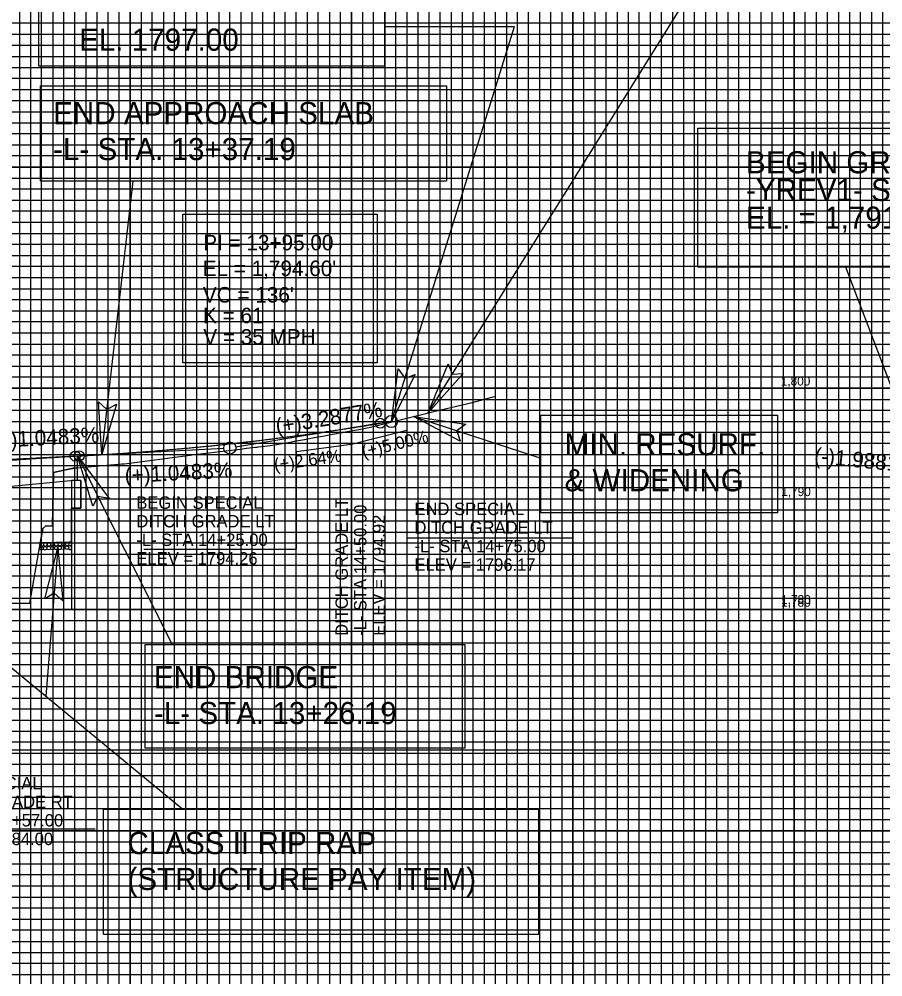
# Model space of a CAD drawing. Extents: x 572269 to 579912, y -56875 to -49627.
# Drawn here: x 574184.5 to 574574.7, y -53513.8 to -53080.9 of the extents above; entities that cross this region are included whole.
import ezdxf

# ---------------------------------------------------------------- set-up
doc = ezdxf.new("R2010")
doc.units = 0
for name, color, linetype in [('Default', 7, 'Continuous'), ('Exist Profile Cell', 7, 'Continuous'), ('Exist Vertical Profile Ground Line', 7, 'Continuous'), ('Pattern 9', 7, 'Continuous'), ('Prop Grid Mask', 7, 'Continuous'), ('Prop PFL Text', 7, 'Continuous'), ('Prop Rip Rap Related Quantities Text', 7, 'Continuous'), ('Prop Roadway Bridge', 7, 'Continuous'), ('Prop Vertical Profile Curve Label', 7, 'Continuous'), ('Prop Vertical Profile Ditch Grade Left', 7, 'Continuous'), ('Prop Vertical Profile Ditch Grade Left Label', 7, 'Continuous'), ('Prop Vertical Profile Ditch Grade Right Label', 7, 'Continuous'), ('Prop Vertical Profile Grade', 7, 'Continuous'), ('Prop Vertical Profile Grade Label', 7, 'Continuous'), ('Prop VPI Label', 7, 'Continuous'), ('Scratch_Level_0', 7, 'Continuous'), ('Scratch_Level_6', 7, 'Continuous'), ('Sheet Cutting Line CELL', 7, 'Continuous'), ('Sheet DOT Grid CELL', 7, 'Continuous'), ('Sheet Profile Grid Major CELL', 7, 'Continuous'), ('Sheet Profile Grid Middle CELL', 7, 'Continuous'), ('Sheet Profile Grid Minor CELL', 7, 'Continuous'), ('Typical Terminator CELL', 7, 'Continuous')]:
    doc.layers.add(name, color=color, linetype=linetype)

# ---------------------------------------------------------------- blocks, each defined once
blk = doc.blocks.new('TERMINATOR')
at = {"layer": 'Typical Terminator CELL'}
blk.add_lwpolyline([(-0.4687, 0.0807), (0, 0), (-0.4713, -0.0833), (-0.4114, 0)], close=True, dxfattribs=at)
blk = doc.blocks.new('PROFILE SHEET SINGLE')
at = {"layer": 'Sheet DOT Grid CELL'}
for p, q in [((7, 21), (7, 0.5)), ((8, 21), (8, 0.5)), ((9, 21), (9, 0.5)), ((10, 21), (10, 0.5)), ((11, 21), (11, 0.5)), ((12, 21), (12, 0.5)), ((13, 21), (13, 0.5)), ((14, 21), (14, 0.5)), ((0, 14.5), (30, 14.5)), ((0, 13.5), (30, 13.5)), ((0, 12.5), (30, 12.5)), ((0, 11.5), (30, 11.5)), ((0, 10.5), (30, 10.5)), ((0, 9.5), (30, 9.5)), ((0, 8.5), (30, 8.5)), ((0, 7.5), (30, 7.5)), ((0, 6.5), (30, 6.5))]:
    blk.add_line(p, q, dxfattribs=at)
at = {"layer": 'Sheet Profile Grid Major CELL'}
for points in [[(7, 21), (7, 0.5), (8, 0.5), (8, 21)], [(9, 21), (9, 0.5), (10, 0.5), (10, 21)], [(11, 21), (11, 0.5), (12, 0.5), (12, 21)], [(13, 21), (13, 0.5), (14, 0.5), (14, 21)], [(30, 13.5), (0, 13.5), (0, 14.5), (30, 14.5)], [(30, 11.5), (0, 11.5), (0, 12.5), (30, 12.5)], [(30, 9.5), (0, 9.5), (0, 10.5), (30, 10.5)], [(30, 7.5), (0, 7.5), (0, 8.5), (30, 8.5)], [(30, 5.5), (0, 5.5), (0, 6.5), (30, 6.5)]]:
    blk.add_lwpolyline(points, dxfattribs=at)
at = {"layer": 'Sheet Profile Grid Middle CELL'}
for points in [[(6.5, 21), (6.5, 0.5), (7.5, 0.5), (7.5, 21)], [(8.5, 21), (8.5, 0.5), (9.5, 0.5), (9.5, 21)], [(10.5, 21), (10.5, 0.5), (11.5, 0.5), (11.5, 21)], [(12.5, 21), (12.5, 0.5), (13.5, 0.5), (13.5, 21)], [(14.5, 21), (14.5, 0.5), (15.5, 0.5), (15.5, 21)], [(30, 15), (0, 15), (0, 14), (30, 14)], [(30, 13), (0, 13), (0, 12), (30, 12)], [(30, 11), (0, 11), (0, 10), (30, 10)], [(30, 9), (0, 9), (0, 8), (30, 8)], [(30, 7), (0, 7), (0, 6), (30, 6)]]:
    blk.add_lwpolyline(points, dxfattribs=at)
at = {"layer": 'Sheet Profile Grid Minor CELL'}
for points in [[(7.1, 21), (7.1, 0.5), (7.2, 0.5), (7.2, 21)], [(7.3, 21), (7.3, 0.5), (7.4, 0.5), (7.4, 21)], [(7.6, 21), (7.6, 0.5), (7.9, 0.5), (7.9, 21)], [(8.1, 21), (8.1, 0.5), (8.2, 0.5), (8.2, 21)], [(8.3, 21), (8.3, 0.5), (8.4, 0.5), (8.4, 21)], [(8.6, 21), (8.6, 0.5), (8.7, 0.5), (8.7, 21)], [(8.8, 21), (8.8, 0.5), (8.9, 0.5), (8.9, 21)], [(9.1, 21), (9.1, 0.5), (9.2, 0.5), (9.2, 21)], [(9.3, 21), (9.3, 0.5), (9.4, 0.5), (9.4, 21)], [(9.6, 21), (9.6, 0.5), (9.7, 0.5), (9.7, 21)], [(9.8, 21), (9.8, 0.5), (9.9, 0.5), (9.9, 21)], [(10.1, 21), (10.1, 0.5), (10.2, 0.5), (10.2, 21)], [(10.3, 21), (10.3, 0.5), (10.4, 0.5), (10.4, 21)], [(10.6, 21), (10.6, 0.5)], [(7.7, 21), (7.7, 0.5), (7.8, 0.5), (7.8, 21)], [(7.7, 20.988), (7.7, 0.5), (7.8, 0.5), (7.8, 20.988)], [(10.7, 21), (10.7, 0.5), (10.8, 0.5), (10.8, 21), (10.9, 21), (10.9, 0.5), (11.1, 0.5), (11.1, 21), (11.2, 21), (11.2, 0.5), (11.3, 0.5), (11.3, 21), (11.4, 21), (11.4, 0.5)], [(11.6, 0.5), (11.6, 21)], [(11.7, 21), (11.7, 0.5), (11.8, 0.5), (11.8, 21)], [(11.9, 21), (11.9, 0.5), (12.1, 0.5), (12.1, 21)], [(12.2, 21), (12.2, 0.5), (12.2, 0.5), (12.3, 0.5), (12.3, 21)], [(12.4, 21), (12.4, 0.5), (12.6, 0.5), (12.6, 21)], [(12.7, 21), (12.7, 0.5), (12.8, 0.5), (12.8, 21)], [(12.9, 21), (12.9, 0.5), (13.1, 0.5), (13.1, 21)], [(13.2, 21), (13.2, 0.5), (13.3, 0.5), (13.3, 21)], [(13.4, 21), (13.4, 0.5), (13.6, 0.5), (13.6, 21)], [(13.7, 21), (13.7, 0.5), (13.8, 0.5), (13.8, 21)], [(13.9, 21), (13.9, 0.5), (14.1, 0.5), (14.1, 21)], [(14.2, 21), (14.2, 0.5), (14.3, 0.5), (14.3, 21)], [(14.4, 21), (14.4, 0.5), (14.6, 0.5), (14.6, 21)], [(14.7, 21), (14.7, 0.5), (14.8, 0.5), (14.8, 21)], [(29, 14.8), (1, 14.8), (1, 14.7), (29, 14.7)], [(29, 14.6), (1, 14.6), (1, 14.4), (29, 14.4)], [(29, 14.3), (1, 14.3), (1, 14.2), (29, 14.2)], [(29, 14.1), (1, 14.1), (1, 13.9), (29, 13.9)], [(29, 13.8), (1, 13.8), (1, 13.7), (29, 13.7)], [(29, 13.6), (1, 13.6), (1, 13.4), (29, 13.4)], [(29, 13.3), (1, 13.3), (1, 13.2), (29, 13.2)], [(29, 13.1), (1, 13.1), (1, 12.9), (29, 12.9)], [(29, 12.8), (1, 12.8), (1, 12.7), (29, 12.7)], [(29, 12.6), (1, 12.6), (1, 12.4), (29, 12.4)], [(29, 12.3), (1, 12.3), (1, 12.2), (29, 12.2)], [(29, 12.1), (1, 12.1), (1, 11.9), (29, 11.9)], [(29, 11.8), (1, 11.8), (1, 11.7), (29, 11.7)], [(29, 11.6), (1, 11.6), (1, 11.4), (29, 11.4)], [(29, 11.3), (1, 11.3), (1, 11.2), (29, 11.2)], [(29, 11.1), (1, 11.1), (1, 10.9), (29, 10.9)], [(29, 10.8), (1, 10.8), (1, 10.7), (29, 10.7)], [(29, 10.6), (1, 10.6)], [(1, 10.4), (29, 10.4)], [(29, 10.3), (1, 10.3), (1, 10.2), (29, 10.2)], [(29, 10.1), (1, 10.1), (1, 9.9), (29, 9.9)], [(29, 9.8), (1, 9.8), (1, 9.7), (29, 9.7)], [(29, 9.6), (1, 9.6), (1, 9.4), (29, 9.4)], [(29, 9.3), (1, 9.3), (1, 9.2), (29, 9.2)], [(29, 9.1), (1, 9.1), (1, 8.9), (29, 8.9)], [(29, 8.8), (1, 8.8), (1, 8.7), (29, 8.7)], [(29, 8.6), (1, 8.6), (1, 8.4), (29, 8.4)], [(29, 8.3), (1, 8.3), (1, 8.2), (29, 8.2)], [(29, 8.1), (1, 8.1), (1, 7.9), (29, 7.9)], [(29, 7.8), (1, 7.8), (1, 7.7), (29, 7.7)], [(29, 7.6), (1, 7.6), (1, 7.4), (29, 7.4)], [(29, 7.3), (1, 7.3), (1, 7.2), (29, 7.2)], [(29, 7.1), (1, 7.1), (1, 6.9), (29, 6.9)], [(29, 6.8), (1, 6.8), (1, 6.7), (29, 6.7)], [(29, 6.6), (1, 6.6), (1, 6.4), (29, 6.4)], [(29, 6.3), (1, 6.3), (1, 6.2), (29, 6.2)]]:
    blk.add_lwpolyline(points, dxfattribs=at)

msp = doc.modelspace()

# ---------------------------------------------------------------- linework, layer by layer
at = {"layer": 'Exist Profile Cell'}
msp.add_line((573884.69, -53397.71), (574399.37, -53397.71), dxfattribs=at)
at = {"layer": 'Exist Vertical Profile Ground Line'}
msp.add_lwpolyline([(574164.26, -53344.81), (574189.32, -53344.81), (574195.16, -53311.03), (574196.51, -53309.87), (574199.61, -53310.05), (574200.02, -53285.74), (574209.57, -53283.74), (574210.56, -53283.66), (574230.95, -53281.92), (574232.15, -53281.82), (574261.81, -53277.96), (574262.62, -53277.83), (574280.54, -53275.63), (574284.48, -53275.16), (574287.2, -53274.84), (574289.92, -53274.51), (574291.3, -53274.35), (574292, -53274.26), (574292.64, -53274.19), (574295.36, -53273.86), (574298.08, -53273.54), (574299.69, -53273.34), (574300.79, -53273.16), (574303.51, -53272.66), (574306.23, -53272.16), (574308.95, -53271.66), (574311.67, -53271.16), (574314.38, -53270.66), (574317.1, -53270.15), (574319.82, -53269.65), (574322.54, -53269.15), (574325.26, -53268.64), (574327.97, -53268.13), (574329.15, -53267.92), (574330.69, -53267.67), (574331.07, -53267.61), (574333.41, -53267.17), (574336.13, -53266.66), (574338.85, -53266.15), (574341.57, -53265.63), (574342.72, -53265.41), (574372.48, -53258.11), (574389.25, -53254.07), (574399.35, -53251.44)], dxfattribs=at)
at = {"layer": 'Pattern 9'}
for p, q in [((574209.69, -53289.42), (574209.69, -53283.71)), ((574210.88, -53289.42), (574210.88, -53283.64)), ((574212.38, -53289.42), (574209.69, -53289.42)), ((574212.38, -53289.42), (574210.88, -53289.42)), ((574212.38, -53301.92), (574212.38, -53289.42)), ((574212.38, -53301.92), (574212.38, -53289.42)), ((574208.13, -53317.21), (574208.13, -53301.92)), ((574208.13, -53301.92), (574212.38, -53301.92)), ((574208.13, -53317.21), (574208.13, -53301.92)), ((574208.13, -53301.92), (574212.38, -53301.92)), ((574194.03, -53317.56), (574208.13, -53317.21)), ((574194.03, -53317.56), (574208.13, -53317.21))]:
    msp.add_line(p, q, dxfattribs=at)
for points in [[(574210.88, -53283.64), (574200.02, -53285.74), (574199.61, -53310.05), (574196.51, -53309.87), (574195.16, -53311.03), (574194.03, -53317.56)], [(574209.69, -53283.71), (574200.02, -53285.74), (574199.61, -53310.05), (574196.51, -53309.87), (574195.16, -53311.03), (574194.03, -53317.56)]]:
    msp.add_lwpolyline(points, dxfattribs=at)
at = {"layer": 'Prop Grid Mask'}
for points in [[(574193.47, -53041.08), (574349.65, -53041.08), (574349.65, -53102.18), (574193.47, -53102.18)], [(574194.12, -53110.93), (574377.54, -53110.93), (574377.54, -53154.11), (574194.12, -53154.11)], [(574491.18, -53130.09), (574676.93, -53130.09), (574676.93, -53192.94), (574491.18, -53192.94)], [(574258.41, -53169.05), (574346.25, -53169.05), (574346.25, -53236.25), (574258.41, -53236.25)], [(574420.22, -53259.88), (574527.12, -53259.88), (574527.12, -53304.03), (574420.22, -53304.03)], [(574241.44, -53363.58), (574385.91, -53363.58), (574385.91, -53410.33), (574241.44, -53410.33)], [(574222.61, -53437.99), (574419.17, -53437.99), (574419.17, -53494.57), (574222.61, -53494.57)]]:
    msp.add_lwpolyline(points, close=True, dxfattribs=at)
at = {"layer": 'Prop PFL Text'}
for p, q in [((574369.36, -53258.86), (574489.62, -53065.71)), ((574349.65, -53084.14), (574408.28, -53084.14)), ((574352.69, -53262.71), (574408.28, -53084.14)), ((574221.88, -53277.7), (574235.97, -53154.11)), ((574594.63, -53289.61), (574558.07, -53192.94)), ((574362.72, -53260.5), (574420.22, -53279.34)), ((574210.88, -53278.32), (574253.71, -53363.58)), ((574116.31, -53320.63), (574258.52, -53437.99)), ((574201.99, -53319.89), (574196.59, -53386.88))]:
    msp.add_line(p, q, dxfattribs=at)
at = {"layer": 'Prop Rip Rap Related Quantities Text'}
for centre in [(574194.74, -53318.36), (574196.37, -53318.34), (574198, -53318.29), (574199.64, -53318.25), (574201.27, -53318.2), (574202.82, -53319.85), (574202.91, -53318.16), (574204.45, -53319.81), (574204.55, -53318.12), (574206.1, -53319.77), (574206.19, -53318.08), (574194.65, -53320.04), (574196.28, -53320.02), (574197.9, -53319.97), (574199.54, -53319.93), (574201.17, -53319.89)]:
    msp.add_circle(centre, 0.82, dxfattribs=at)
for centre in [(574207.44, -53319.74), (574207.53, -53318.06)]:
    msp.add_arc(centre, 0.82, 216.348, 145.8038, dxfattribs=at)
at = {"layer": 'Prop Roadway Bridge'}
for p, q in [((574210.88, -53289.42), (574210.88, -53278.32)), ((574109.69, -53298.44), (574210.88, -53289.17)), ((574208.13, -53289.42), (574208.13, -53301.92)), ((574212.38, -53289.42), (574208.13, -53289.42)), ((574212.38, -53289.42), (574212.38, -53301.92)), ((574208.13, -53301.92), (574208.13, -53347.45)), ((574212.38, -53301.92), (574208.13, -53301.92)), ((574208.13, -53317.21), (574194.03, -53317.56))]:
    msp.add_line(p, q, dxfattribs=at)
at = {"layer": 'Prop Vertical Profile Curve Label'}
for centre in [(574347.69, -53263.53), (574209.86, -53278.37), (574211.69, -53278.27)]:
    msp.add_circle(centre, 2.25, dxfattribs=at)
at = {"layer": 'Prop Vertical Profile Ditch Grade Left'}
for p, q in [((574359.69, -53266.86), (574334.69, -53273.11)), ((574334.69, -53273.11), (574309.69, -53276.41))]:
    msp.add_line(p, q, dxfattribs=at)
at = {"layer": 'Prop Vertical Profile Ditch Grade Left Label'}
for p, q in [((574359.69, -53266.86), (574359.69, -53315.34)), ((574334.69, -53273.11), (574334.69, -53360.82)), ((574309.69, -53276.41), (574309.69, -53320.45)), ((574359.69, -53315.34), (574434.92, -53315.34)), ((574240.91, -53320.45), (574309.69, -53320.45))]:
    msp.add_line(p, q, dxfattribs=at)
at = {"layer": 'Prop Vertical Profile Ditch Grade Right Label'}
msp.add_line((574141.69, -53446.92), (574218.83, -53446.92), dxfattribs=at)
at = {"layer": 'Prop Vertical Profile Grade'}
for p, q in [((574347.69, -53263.53), (574352.69, -53262.71)), ((574209.86, -53278.37), (574211.69, -53278.27))]:
    msp.add_line(p, q, dxfattribs=at)
for points in [[(574211.69, -53278.27), (574214.41, -53278.13), (574217.13, -53277.98), (574219.85, -53277.82), (574222.57, -53277.65), (574225.29, -53277.48), (574228.01, -53277.31), (574230.73, -53277.13), (574233.45, -53276.94), (574236.17, -53276.74), (574238.89, -53276.54), (574241.61, -53276.34), (574244.33, -53276.12), (574247.05, -53275.9), (574249.77, -53275.68), (574252.49, -53275.45), (574255.21, -53275.21), (574257.93, -53274.97), (574260.65, -53274.72), (574263.37, -53274.46), (574266.09, -53274.2), (574268.81, -53273.94), (574271.53, -53273.66), (574274.25, -53273.38), (574276.97, -53273.1), (574279.69, -53272.8), (574282.41, -53272.51), (574285.13, -53272.2), (574287.85, -53271.89), (574290.57, -53271.58), (574293.29, -53271.25), (574296.01, -53270.93), (574298.73, -53270.59), (574301.45, -53270.25), (574304.17, -53269.9), (574306.89, -53269.55), (574309.61, -53269.19), (574312.33, -53268.83), (574315.05, -53268.46), (574317.77, -53268.08), (574320.49, -53267.7), (574323.21, -53267.31), (574325.93, -53266.91), (574328.65, -53266.51), (574331.37, -53266.1), (574334.09, -53265.69), (574336.81, -53265.27), (574339.53, -53264.84), (574342.25, -53264.41), (574344.97, -53263.97), (574347.69, -53263.53)], [(574114.86, -53286.19), (574116.76, -53285.98), (574118.66, -53285.77), (574120.56, -53285.56), (574122.46, -53285.36), (574124.36, -53285.15), (574126.26, -53284.95), (574128.16, -53284.75), (574130.06, -53284.56), (574131.96, -53284.36), (574133.86, -53284.17), (574135.76, -53283.98), (574137.66, -53283.79), (574139.56, -53283.61), (574141.46, -53283.43), (574143.36, -53283.25), (574145.26, -53283.07), (574147.16, -53282.89), (574149.06, -53282.72), (574150.96, -53282.55), (574152.86, -53282.38), (574154.76, -53282.21), (574156.66, -53282.05), (574158.56, -53281.89), (574160.46, -53281.73), (574162.36, -53281.57), (574164.26, -53281.41), (574166.16, -53281.26), (574168.06, -53281.11), (574169.96, -53280.96), (574171.86, -53280.82), (574173.76, -53280.67), (574175.66, -53280.53), (574177.56, -53280.39), (574179.46, -53280.25), (574181.36, -53280.12), (574183.26, -53279.99), (574185.16, -53279.86), (574187.06, -53279.73), (574188.96, -53279.6), (574190.86, -53279.48), (574192.76, -53279.36), (574194.66, -53279.24), (574196.56, -53279.12), (574198.46, -53279.01), (574200.36, -53278.89), (574202.26, -53278.79), (574204.16, -53278.68), (574206.06, -53278.57), (574207.96, -53278.47), (574209.86, -53278.37)]]:
    msp.add_spline(points, degree=3, dxfattribs=at)
at = {"layer": 'Prop VPI Label'}
for p, q in [((574347.69, -53263.53), (574282.4, -53274.26)), ((574211.69, -53278.27), (574276.94, -53274.85)), ((574209.86, -53278.37), (574165.1, -53280.71))]:
    msp.add_line(p, q, dxfattribs=at)
for centre in [(574352.69, -53262.71), (574279.69, -53274.71)]:
    msp.add_circle(centre, 2.75, dxfattribs=at)
at = {"layer": 'Scratch_Level_0'}
for p, q in [((575012.91, -53411.24), (573884.69, -53411.24)), ((573884.69, -53497.71), (575215.07, -53497.71))]:
    msp.add_line(p, q, dxfattribs=at)
at = {"layer": 'Scratch_Level_6'}
msp.add_line((576826.8, -53347.71), (572993.85, -53347.71), dxfattribs=at)

# ---------------------------------------------------------------- block references
at = {"layer": 'Prop PFL Text'}
for p, xscale, yscale, rotation in [((574369.36, -53258.86), 49.99999999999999, 49.99999999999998, -121.93220004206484), ((574352.69, -53262.71), 50.000000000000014, 49.999999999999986, -107.28913136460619), ((574221.88, -53277.7), 50.00000000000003, 50.000000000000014, -96.49966000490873), ((574362.72, -53260.5), 50, 49.99999999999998, 161.87111900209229), ((574210.88, -53278.32), 50.00000000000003, 50.00000000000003, 116.66899255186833), ((574201.99, -53319.89), 50.00000000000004, 50.00000000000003, 85.38427064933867)]:
    msp.add_blockref('TERMINATOR', p, dxfattribs=dict(at, xscale=xscale, yscale=yscale, rotation=rotation))
at = {"layer": 'Sheet Cutting Line CELL', "xscale": 50, "yscale": 50}
msp.add_blockref('PROFILE SHEET SINGLE', (573834.69, -53822.71), dxfattribs=at)

# ---------------------------------------------------------------- texts
at = {"layer": 'Default'}
for s, p in [('1,800', (574528.61, -53246.46)), ('1,790', (574528.83, -53296.46)), ('1,780', (574528.77, -53345.21)), ('1,780', (574528.77, -53346.46))]:
    msp.add_text(s, height=4, dxfattribs=at).set_placement(p)
at = {"layer": 'Prop PFL Text'}
for s, p in [('EL. 1797.00', (574211.61, -53095.12)), ('END APPROACH SLAB', (574199.88, -53128.34)), ('-L- STA. 13+37.19', (574199.88, -53144.59)), ('BEGIN GRADE', (574512.92, -53150.54)), ('-YREV1- STA.10+09.94', (574512.92, -53163.06)), ('EL. = 1,791.62', (574512.92, -53175.58)), ('MIN. RESURF.', (574430.97, -53278.02)), ('& WIDENING', (574430.97, -53294.27)), ('END BRIDGE', (574245.43, -53383.27)), ('-L- STA. 13+26.19', (574245.43, -53399.52)), ('CLASS II RIP RAP', (574233.47, -53458.25)), ('(STRUCTURE PAY ITEM)', (574233.47, -53474.5))]:
    msp.add_text(s, height=10, dxfattribs=at).set_placement(p)
at = {"layer": 'Prop Vertical Profile Curve Label'}
for s, p in [("VC = 136'", (574267.55, -53208.95)), ('K = 61', (574267.61, -53218.29)), ('V = 35 MPH', (574267.74, -53227.98))]:
    msp.add_text(s, height=7, dxfattribs=at).set_placement(p)
at = {"layer": 'Prop Vertical Profile Ditch Grade Left Label'}
for s, rotation, p in [('(+)5.00%', 13.5694, (574340.12, -53279.15)), ('(+)2.64%', 8.0164, (574300.08, -53285.04)), ('DITCH GRADE LT', 90, (574333.03, -53359.62)), ('-L- STA 14+50.00', 90, (574341.43, -53359.62)), ('ELEV = 1794.92', 90, (574349.83, -53359.62))]:
    msp.add_text(s, height=5.6, rotation=rotation, dxfattribs=at).set_placement(p)
for s, p in [('BEGIN SPECIAL', (574237.49, -53302.19)), ('END SPECIAL', (574363.12, -53305.02)), ('DITCH GRADE LT', (574237.49, -53310.59)), ('DITCH GRADE LT', (574363.12, -53313.42)), ('-L- STA 14+25.00', (574237.49, -53318.99)), ('-L- STA 14+75.00', (574363.12, -53321.82)), ('ELEV = 1794.26', (574237.49, -53327.39)), ('ELEV = 1796.17', (574363.12, -53330.22))]:
    msp.add_text(s, height=5.6, dxfattribs=at).set_placement(p)
at = {"layer": 'Prop Vertical Profile Ditch Grade Right Label'}
for s, p in [('END SPECIAL', (574145.12, -53428.99)), ('DITCH GRADE RT', (574145.12, -53437.39)), ('-L- STA 12+57.00', (574145.12, -53445.79)), ('ELEV = 1784.00', (574145.12, -53454.19))]:
    msp.add_text(s, height=5.6, dxfattribs=at).set_placement(p)
at = {"layer": 'Prop Vertical Profile Grade Label'}
for s, rotation, p in [('(+)3.2877%', 9.335, (574301, -53268.42)), ('(+)1.0483%', 3.0005, (574172.25, -53274.72)), ('(-)1.9881%', 354.3232, (574543.52, -53281.51)), ('(+)1.0483%', 3.0005, (574232.39, -53290.57))]:
    msp.add_text(s, height=7, rotation=rotation, dxfattribs=at).set_placement(p)
at = {"layer": 'Prop VPI Label'}
for s, p in [('PI = 13+95.00', (574267.71, -53185.35)), ("EL = 1,794.60'", (574267.45, -53197))]:
    msp.add_text(s, height=7, dxfattribs=at).set_placement(p)

doc.saveas('drawing.dxf')
